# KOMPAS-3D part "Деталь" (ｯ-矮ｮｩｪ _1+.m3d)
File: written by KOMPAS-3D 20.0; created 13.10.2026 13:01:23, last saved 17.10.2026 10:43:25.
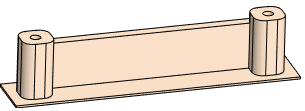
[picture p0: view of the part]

Document properties: Полное имя файла: D:\RicWork\Project-EPS32\box_compas\корпус\п-стойка_1+.m3d

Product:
- Part/product: Деталь
    Масса: 0.0122773
  - Body: Тело 1
      Масса: 0.00935935

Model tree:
1. Эскиз:1
2. Элемент выдавливания:1
     Расстояние 1 = 11
3. Эскиз:2  (with: Элемент выдавливания:1)
4. Элемент выдавливания:2
     Расстояние 2 = 11
5. Массив по сетке:1  (with: Элемент выдавливания:2, Эскиз:2)  (2 pattern instances)
     Шаг 1 = 10; Угол раствора = -90; Шаг 2 = 44.2
6. Эскиз:3  (with: Элемент выдавливания:1)
7. Элемент выдавливания:3
     Расстояние 2 = 2
8. Эскиз:4  (with: Элемент выдавливания:1)
9. Элемент выдавливания:4
     Расстояние 2 = 2
10. Скругление:1  (with: Элемент выдавливания:1)
     Радиус = 2
11. Элемент выдавливания:5  (with: Элемент выдавливания:3)
     Расстояние 1 = 2
12. Эскиз:5  (with: Элемент выдавливания:1)
13. Элемент выдавливания:6
     Расстояние 1 = 0.4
